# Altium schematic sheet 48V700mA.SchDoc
size B; SheetNumber: 0; SheetTotal: 0
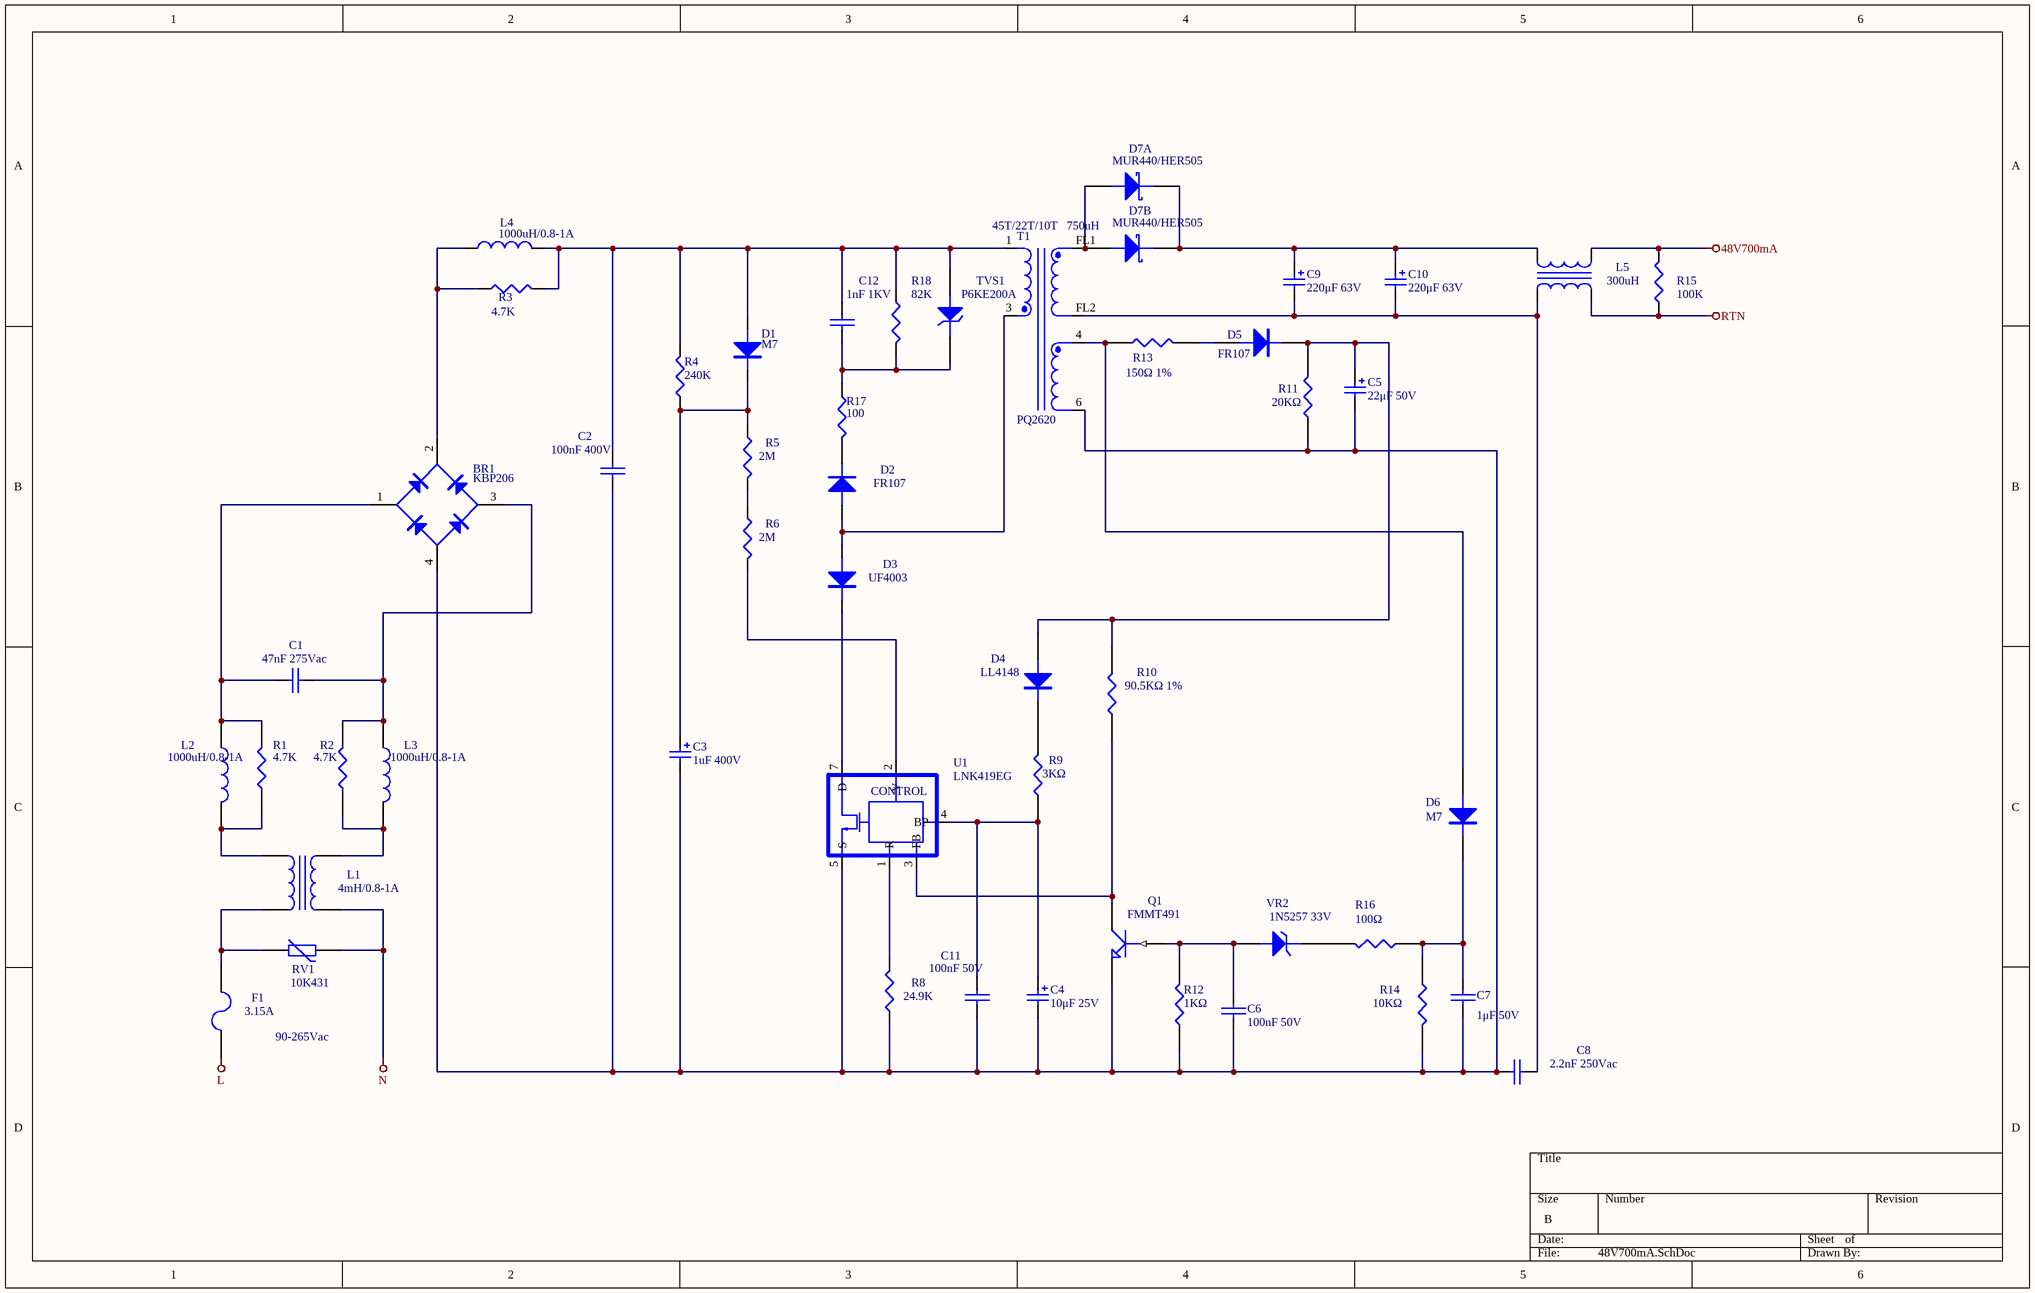
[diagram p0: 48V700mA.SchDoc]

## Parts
BR1  KBP206  [KBP206G]
C1  47nF 275Vac  [rad0.4]
C2  100nF 400V  [rad0.4]
C3  1uF 400V  [RB7.6-15]
C4  10μF 25V  [rb.1/.2]
C5  22μF 50V  [RB7.6-15]
C6  100nF 50V  [0805C]
C7  1μF 50V  [0805C]
C8  2.2nF 250Vac  [RAD0.4]
C9  220μF 63V  [RB7.6-15]
C10  220μF 63V  [RB7.6-15]
C11  100nF 50V  [0805C]
C12  1nF 1KV  [RAD0.2]
D1  M7  [SMA]
D2  FR107  [DO-35]
D3  UF4003  [DO-35]
D4  LL4148  [DO-213AA]
D5  FR107  [DO-35]
D6  M7  [SMA]
D7A  MUR440/HER505  [do-35]
D7B  MUR440/HER505  [DO-35]
F1  3.15A  [RAD0.2]
L1  4mH/0.8-1A  [UU16]
L2  1000uH/0.8-1A  [l1016]
L3  1000uH/0.8-1A  [l1016]
L4  1000uH/0.8-1A  [l1016]
L5  300uH  [UU9.8]
Q1  FMMT491  [SOT-23Q]
R1  4.7K  [0805R]
R2  4.7K  [0805R]
R3  4.7K  [0805R]
R4  240K  [1206R]
R5  2M  [1206R]
R6  2M  [1206R]
R8  24.9K  [0805R]
R9  3KΩ  [1206R]
R10  90.5KΩ 1%  [0805R]
R11  20KΩ  [0805R]
R12  1KΩ  [0805R]
R13  150Ω 1%  [0805R]
R14  10KΩ  [0805R]
R15  100K  [1206R]
R16  100Ω  [0805R]
R17  100  [1206R]
R18  82K  [1206R]
RV1  10K431  [rad0.4]
T1  PQ2620  [PQ2620-3220]
TVS1  P6KE200A  [do-35]
U1  LNK419EG  [eSIP-7C]
VR2  1N5257 33V  [DO-35]

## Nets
48V700mA: L5.4 R15.2
L: F1.1
N: L1.4 RV1.2
RTN: L5.3 R15.1
NetBR1_1: BR1.1(AC) C1.1 L2.1 R1.2
NetBR1_2: BR1.2(V+) L4.1 R3.1
NetBR1_3: BR1.3(AC) C1.2 L3.1 R2.2
NetBR1_4: BR1.4(V-) C2.2 C3.2 C4.2 C5.2 C6.2 C7.2 C8.1 C11.2 Q1.3(E) R8.1 R11.1 R12.1 R14.2 T1.6 U1.5(S)
NetC2_1: C2.1 C12.1 D1.1(A) L4.2 R3.2 R4.2 R18.1 T1.1 TVS1.1(A)
NetC3_1: C3.1 D1.2(K) R4.1 R5.1
NetC4_1: C4.1 C11.1 R9.1 U1.4(BP)
NetC5_1: C5.1 D4.1(A) D5.2(K) R10.2 R11.2
NetC6_1: C6.1 Q1.1(B) R12.2 VR2.1(A)
NetC7_1: C7.1 D6.2(K) R14.1 R16.1
NetC8_2: C8.2 C9.2 C10.2 L5.1 T1.FL2
NetC9_1: C9.1 C10.1 D7A.2(K) D7B.2(K) L5.2
NetC12_2: C12.2 R17.1 R18.2 TVS1.2(K)
NetD2_1: D2.1(A) D3.1(A) T1.3
NetD2_2: D2.2(K) R17.2
NetD3_2: D3.2(K) U1.7(D)
NetD4_2: D4.2(K) R9.2
NetD5_1: D5.1(A) R13.2
NetD6_1: D6.1(A) R13.1 T1.4
NetD7A_1: D7A.1(A) D7B.1(A) T1.FL1
NetF1_2: F1.2 L1.3 RV1.1
NetL1_1: L1.1 L2.2 R1.1
NetL1_2: L1.2 L3.2 R2.1
NetQ1_2: Q1.2(C) R10.1 U1.3(FB)
NetR5_2: R5.2 R6.1
NetR6_2: R6.2 U1.2(V)
NetR8_2: R8.2 U1.1(R)
NetR16_2: R16.2 VR2.2(K)

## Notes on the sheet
- 90-265Vac

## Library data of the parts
BR1 = BRIDGE1: Diode Bridge
C1 C2 C6-C8 C11 C12 = CAP: Capacitor
C3-C5 C9 C10 = Cap Pol1: Polarized Capacitor (Radial); Value: 100pF
D1-D6 = DIODE
D7A D7B = DIODE SCHOTTKY: Schottky Diode
F1 = FUSE2: Fuse
L1 L5 = TRANS1
L2-L4 = INDUCTOR
Q1 = NPN1: NPN Transistor
R1-R6 R8-R18 = RES1
RV1 = VARISTOR
T1 = T1
TVS1 VR2 = ZENER3: Zener Diode
U1 = LNK40XEG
